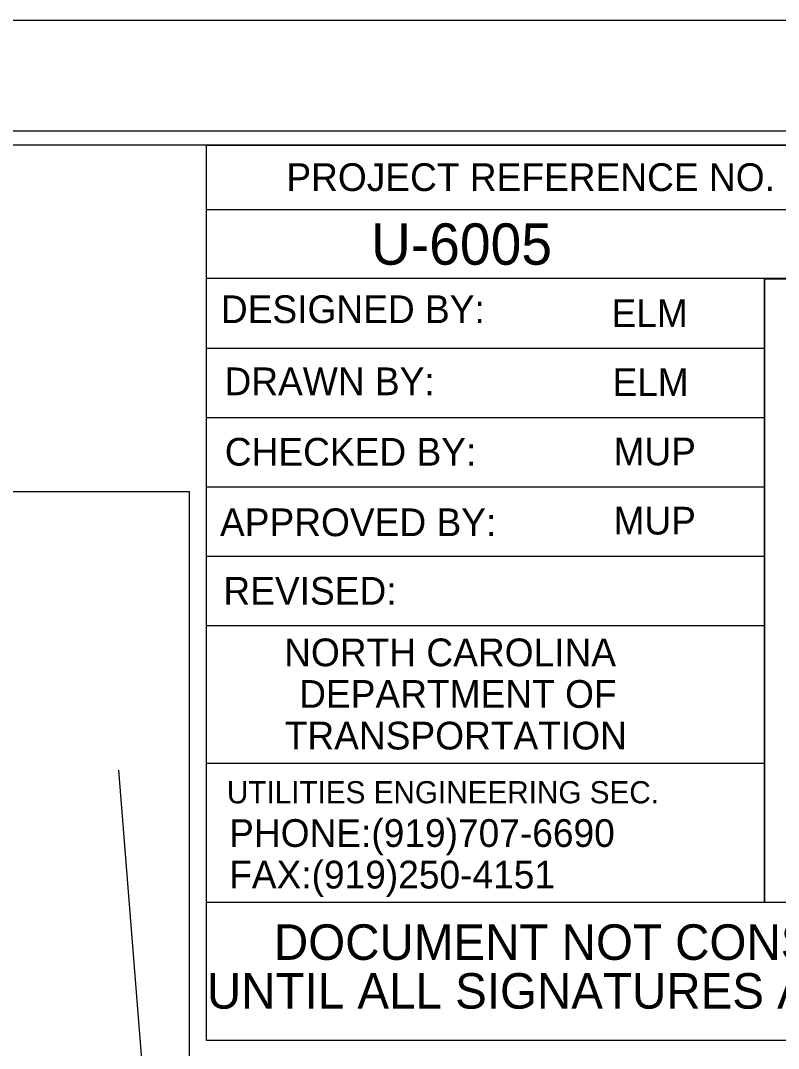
# Model space of a CAD drawing. Extents: x 0 to 7954, y -383 to 1504.
# Drawn here: x 2.4159 to 2.644, y 1.5238 to 1.8333 of the extents above; entities that cross this region are included whole.
import ezdxf

# ---------------------------------------------------------------- set-up
doc = ezdxf.new("R2010")
doc.units = 0
for name, color, linetype in [('Scratch_Level_3', 7, 'Continuous'), ('UC Plan Profile Sheet 34 CELL', 7, 'Continuous'), ('UC Plan Sheet 34 CELL', 7, 'Continuous'), ('UE Plan Profile Sheet 34 CELL', 7, 'Continuous')]:
    doc.layers.add(name, color=color, linetype=linetype)

msp = doc.modelspace()

# ---------------------------------------------------------------- linework, layer by layer
at = {"layer": 'Scratch_Level_3'}
msp.add_lwpolyline([(0.36636, 0.9085), (0.36636, 1.69148), (2.46666, 1.69148), (2.46666, 1.49966), (2.75747, 1.49966), (2.75747, 0.9085)], close=True, dxfattribs=at)
at = {"layer": 'UC Plan Profile Sheet 34 CELL'}
for p, q in [((2.60044, 1.74676), (2.60044, 1.74676)), ((2.49092, 1.03177), (2.4455, 1.60759)), ((2.4719, 1.52621), (2.4719, 1.56775)), ((2.80496, 1.52621), (2.4719, 1.52621))]:
    msp.add_line(p, q, dxfattribs=at)
for points in [[(0.02749, 0.00833), (2.83333, 0.00833), (2.83333, 1.83333), (0.02749, 1.83333)], [(0.04916, 0.04166), (2.82583, 0.04166), (2.82583, 1.8), (0.04916, 1.8)], [(2.80499, 1.79583), (0.30499, 1.79583), (0.30499, 0.04583), (2.80499, 0.04583)]]:
    msp.add_lwpolyline(points, close=True, dxfattribs=at)
at = {"layer": 'UC Plan Sheet 34 CELL'}
for p, q in [((2.4719, 1.77648), (2.80496, 1.77648)), ((2.55581, 1.76604), (2.55581, 1.76604)), ((2.6054, 1.74516), (2.6054, 1.74516)), ((2.4719, 1.7347), (2.63979, 1.7347)), ((2.6054, 1.72427), (2.6054, 1.72427)), ((2.4719, 1.71383), (2.63979, 1.71383)), ((2.6054, 1.70339), (2.6054, 1.70339)), ((2.4719, 1.69295), (2.63979, 1.69295)), ((2.6054, 1.68252), (2.6054, 1.68252)), ((2.4719, 1.67208), (2.63979, 1.67208)), ((2.4719, 1.65118), (2.63979, 1.65118)), ((2.4719, 1.60977), (2.63979, 1.60977))]:
    msp.add_line(p, q, dxfattribs=at)
for points in [[(2.4719, 1.79581), (2.80496, 1.79581), (2.80496, 1.75568)], [(2.80496, 1.75568), (2.4719, 1.75568), (2.4719, 1.79581)], [(2.63979, 1.75568), (2.63979, 1.56775), (2.4719, 1.56775), (2.4719, 1.79581)], [(2.80496, 1.56775), (2.63979, 1.56775), (2.63979, 1.7556), (2.80496, 1.7556)]]:
    msp.add_lwpolyline(points, dxfattribs=at)

# ---------------------------------------------------------------- texts
at = {"layer": 'UC Plan Profile Sheet 34 CELL'}
for s, height, p in [('U-6005', 0.01243, (2.52136, 1.75982)), ('ELM', 0.008333, (2.59379, 1.74103)), ('ELM', 0.008333, (2.59408, 1.72025)), ('MUP', 0.008333, (2.59442, 1.69941)), ('MUP', 0.008333, (2.59442, 1.67858))]:
    msp.add_text(s, height=height, dxfattribs=at).set_placement(p)
at = {"layer": 'UC Plan Sheet 34 CELL'}
for s, height, p in [('PROJECT REFERENCE NO.', 0.0083524, (2.4959, 1.782)), ('DESIGNED BY:', 0.0083524, (2.47619, 1.74223)), ('DRAWN BY:', 0.008352, (2.47727, 1.72052)), ('CHECKED BY:', 0.0083524, (2.47736, 1.69931)), ('APPROVED BY:', 0.0083524, (2.47592, 1.67808)), ('REVISED:', 0.008352, (2.47694, 1.65745)), ('NORTH CAROLINA', 0.0083524, (2.49523, 1.63891)), ('DEPARTMENT OF', 0.0083524, (2.49975, 1.62639)), ('TRANSPORTATION', 0.0083524, (2.4954, 1.61385)), ('UTILITIES ENGINEERING SEC.', 0.0066819, (2.47799, 1.59763)), ('PHONE:(919)707-6690', 0.0083524, (2.47867, 1.58451)), ('FAX:(919)250-4151', 0.0083524, (2.47867, 1.57199))]:
    msp.add_text(s, height=height, dxfattribs=at).set_placement(p)
at = {"layer": 'UE Plan Profile Sheet 34 CELL'}
for s, p in [('DOCUMENT NOT CONSIDERED FINAL ', (2.49215, 1.5505)), ('UNTIL ALL SIGNATURES ARE COMPLETED', (2.47197, 1.53581))]:
    msp.add_text(s, height=0.010697, dxfattribs=at).set_placement(p)

doc.saveas('drawing.dxf')
